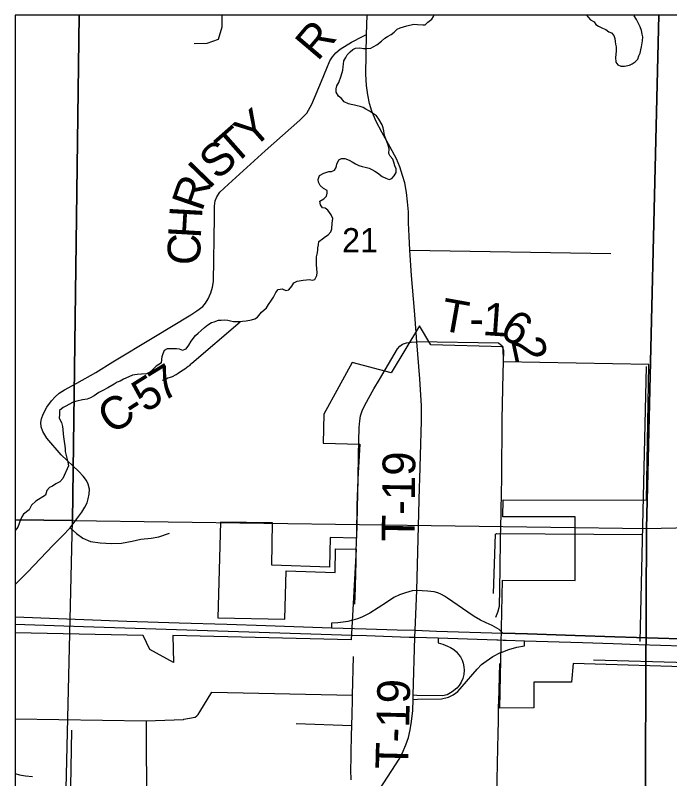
# Model space of a CAD drawing. Extents: x -8.5 to 18.7, y -20.3 to 7.
# Drawn here: x -8.459 to -6.189, y 4.29 to 6.938 of the extents above; entities that cross this region are included whole.
import ezdxf

# ---------------------------------------------------------------- set-up
doc = ezdxf.new("R2010")
doc.units = 0
for name, color, linetype in [('Default', 7, 'Continuous'), ('GM_X_City_Street', 7, 'Continuous'), ('GM_X_Corporation', 7, 'Continuous'), ('GM_X_County_Road', 7, 'Continuous'), ('GM_X_County_Road_Text', 7, 'Continuous'), ('GM_X_Interchange_Ramps', 7, 'Continuous'), ('GM_X_Minor_River', 7, 'Continuous'), ('GM_X_Rail_Line', 7, 'Continuous'), ('GM_X_Section', 7, 'Continuous'), ('GM_X_Section_Text', 7, 'Continuous'), ('GM_X_State_Route', 7, 'Continuous'), ('GM_X_Township_Road', 7, 'Continuous'), ('GM_X_Township_Road_Text', 7, 'Continuous'), ('GM_X_US_Route', 7, 'Continuous'), ('SH_Cut_Line', 7, 'Continuous')]:
    doc.layers.add(name, color=color, linetype=linetype)

msp = doc.modelspace()

# ---------------------------------------------------------------- linework, layer by layer
at = {"layer": 'Default'}
for points in [[(-8.2372, 6.938), (-8.4587, 6.938), (-8.4587, 5.1881), (-8.2602, 5.1852)], [(-6.2268, 6.938), (-8.2372, 6.938), (-8.2602, 5.1852), (-6.2691, 5.158)], [(-5.6649, 6.938), (-6.2268, 6.938), (-6.2691, 5.158), (-5.6605, 5.1719)], [(-8.4587, 5.1881), (-8.4587, 3.1783), (-8.308, 3.1769), (-8.2602, 5.1852)]]:
    msp.add_lwpolyline(points, close=True, dxfattribs=at)
at = {"layer": 'GM_X_City_Street'}
msp.add_line((-7.7774, 4.59), (-7.2888, 4.5798), dxfattribs=at)
for points in [[(-6.0668, 4.6758), (-6.5241, 4.6888), (-6.5294, 4.625), (-6.6599, 4.624), (-6.6607, 4.535), (-6.7778, 4.5349), (-6.7689, 4.9782), (-6.5174, 4.9773), (-6.5167, 5.1981), (-6.7673, 5.1977), (-6.7669, 5.2575), (-6.2701, 5.2558), (-6.262, 5.7269), (-6.7651, 5.7356), (-6.7671, 5.7877), (-7.0173, 5.7946), (-7.0564, 5.8602), (-7.1553, 5.6974), (-7.2898, 5.7334), (-7.3365, 5.6493), (-7.3888, 5.5548), (-7.3906, 5.4537), (-7.2638, 5.4504), (-7.2703, 5.3301), (-7.2751, 5.1245), (-7.3669, 5.1265), (-7.3686, 5.0231), (-7.5689, 5.0299), (-7.5665, 5.1774), (-7.7465, 5.1798), (-7.7558, 4.8481), (-7.5235, 4.8428), (-7.5194, 5.0107), (-7.3489, 5.0049), (-7.3476, 5.0876), (-7.2761, 5.0856), (-7.2937, 4.7709), (-7.9124, 4.786), (-7.9105, 4.6929), (-7.9916, 4.7383), (-8.0153, 4.7862), (-8.4587, 4.7954), (-8.4587, 2.5592)], [(-8.005, 4.4904), (-7.8758, 4.4954), (-7.874, 4.4958), (-7.8344, 4.5033), (-7.8291, 4.5074), (-7.8244, 4.5126), (-7.8187, 4.5211), (-7.7774, 4.59)]]:
    msp.add_lwpolyline(points, dxfattribs=at)
at = {"layer": 'GM_X_Corporation'}
msp.add_lwpolyline([(-0.1911, 6.938), (-8.4587, 6.938), (-8.4587, 1.1732)], dxfattribs=at)
at = {"layer": 'GM_X_County_Road'}
for points in [[(-8.4587, 4.9632), (-8.4161, 5.0061), (-8.3274, 5.0994), (-8.2948, 5.1327), (-8.2688, 5.16), (-8.2448, 5.1908), (-8.228, 5.2142), (-8.2171, 5.2314), (-8.2095, 5.2467), (-8.2054, 5.2608), (-8.2025, 5.2769), (-8.2018, 5.2946), (-8.2059, 5.3109), (-8.2115, 5.3245), (-8.2229, 5.3393), (-8.2382, 5.3554), (-8.2992, 5.413), (-8.3493, 5.4708), (-8.3634, 5.4942), (-8.3687, 5.51), (-8.3697, 5.5248), (-8.3678, 5.5384), (-8.3624, 5.5542), (-8.349, 5.5783), (-8.3332, 5.6004), (-8.3209, 5.614), (-8.3065, 5.6266), (-8.2878, 5.6383), (-8.2457, 5.6619), (-8.1796, 5.6993), (-8.1201, 5.7358), (-7.9781, 5.8213), (-7.8503, 5.8986), (-7.8291, 5.9122), (-7.8087, 5.928), (-7.7985, 5.9397), (-7.79, 5.9545), (-7.7808, 5.9747), (-7.7747, 5.9946), (-7.771, 6.0143), (-7.7678, 6.2389), (-7.7673, 6.2755), (-7.7656, 6.2937), (-7.7602, 6.308), (-7.7491, 6.3241), (-7.7192, 6.3518), (-7.592, 6.4675), (-7.4715, 6.5744), (-7.4474, 6.5978), (-7.4304, 6.6291), (-7.3966, 6.7091), (-7.3781, 6.7545), (-7.3672, 6.7803), (-7.3589, 6.7937), (-7.3473, 6.8078), (-7.3315, 6.8209), (-7.2928, 6.845), (-7.2547, 6.8644), (-7.2401, 6.8715)], [(-7.2173, 4.2203), (-7.1801, 4.2756), (-7.1278, 4.3572), (-7.1165, 4.377), (-7.1045, 4.4075), (-7.0952, 4.433), (-7.089, 4.4597), (-7.0841, 4.4877), (-7.0805, 4.5268), (-7.0793, 4.5648)], [(-8.4587, 4.4971), (-8.005, 4.4904), (-8.0049, 4.4864), (-8.0049, 4.4779)], [(-8.0049, 4.4779), (-8.0048, 4.4525), (-8.0037, 4.213), (-8.0015, 4.203), (-7.996, 4.1926), (-7.9883, 4.1843), (-7.9797, 4.1787), (-7.9712, 4.177), (-7.2987, 4.1876), (-7.2906, 4.1877), (-7.2385, 4.1886)]]:
    msp.add_lwpolyline(points, dxfattribs=at)
at = {"layer": 'GM_X_Interchange_Ramps'}
for points in [[(-7.0665, 4.9422), (-7.0817, 4.9411), (-7.1056, 4.935), (-7.1263, 4.9279), (-7.1454, 4.9181), (-7.1715, 4.9009), (-7.2286, 4.8643), (-7.2564, 4.8506), (-7.2722, 4.8444), (-7.2875, 4.8396)], [(-7.2875, 4.8396), (-7.3048, 4.8352), (-7.3216, 4.8322), (-7.3406, 4.83), (-7.362, 4.829), (-7.3621, 4.8135)], [(-6.9925, 4.7781), (-6.9917, 4.7608), (-6.9759, 4.756), (-6.9596, 4.7497), (-6.949, 4.7444), (-6.9383, 4.7375), (-6.9287, 4.7294), (-6.921, 4.7209), (-6.9144, 4.7124), (-6.9086, 4.7006), (-6.9051, 4.6902), (-6.9025, 4.6772), (-6.9019, 4.6667), (-6.9032, 4.6516), (-6.9068, 4.6376), (-6.9124, 4.6248), (-6.9193, 4.6127), (-6.9278, 4.6033), (-6.9431, 4.5906), (-6.9607, 4.5809), (-6.9773, 4.5774), (-7.0664, 4.5788), (-7.079, 4.5791)], [(-6.7739, 4.7278), (-6.7475, 4.7384), (-6.719, 4.7459), (-6.6926, 4.7507), (-6.6921, 4.7685)], [(-7.0793, 4.5648), (-7.0642, 4.566), (-6.98, 4.5665), (-6.9563, 4.5722), (-6.94, 4.5805), (-6.9242, 4.5924), (-6.9089, 4.609), (-6.8567, 4.67), (-6.8413, 4.6853), (-6.8256, 4.6972), (-6.8023, 4.7134), (-6.776, 4.727), (-6.7739, 4.7278)]]:
    msp.add_lwpolyline(points, dxfattribs=at)
at = {"layer": 'GM_X_Minor_River'}
for p, q in [((-7.8462, 5.7317), (-7.6793, 5.8743)), ((-6.2919, 4.7662), (-6.269, 5.7197)), ((-6.8007, 4.9327), (-6.7934, 5.1384)), ((-6.7934, 5.1384), (-6.7896, 5.1398)), ((-6.7896, 5.1398), (-6.2839, 5.1372)), ((-6.4529, 4.7018), (-6.0649, 4.6916))]:
    msp.add_line(p, q, dxfattribs=at)
for points in [[(-7.1858, 6.3788), (-7.1738, 6.3726), (-7.1624, 6.3688), (-7.1525, 6.3717), (-7.1441, 6.3808), (-7.1372, 6.3922), (-7.1379, 6.4051), (-7.1424, 6.4158), (-7.1461, 6.4279), (-7.1498, 6.4386), (-7.1588, 6.4493), (-7.1626, 6.4584), (-7.1625, 6.4744), (-7.1654, 6.4873), (-7.1691, 6.4965), (-7.1729, 6.5064), (-7.1773, 6.5186), (-7.1795, 6.5277), (-7.181, 6.5368), (-7.1832, 6.5475), (-7.1862, 6.5581), (-7.1982, 6.578), (-7.2057, 6.5887), (-7.2193, 6.5986), (-7.2298, 6.6048), (-7.2427, 6.6124), (-7.2518, 6.6186), (-7.2631, 6.6217), (-7.273, 6.624), (-7.2828, 6.6256), (-7.2934, 6.6287), (-7.3025, 6.6303), (-7.3176, 6.6372), (-7.3274, 6.6487), (-7.3372, 6.6579), (-7.3462, 6.6709), (-7.3461, 6.6823), (-7.343, 6.6929), (-7.3369, 6.7042), (-7.3284, 6.7277), (-7.3229, 6.7475), (-7.3214, 6.7588), (-7.3205, 6.7687), (-7.3189, 6.7801), (-7.3128, 6.7915), (-7.3074, 6.8013), (-7.2975, 6.8111), (-7.2883, 6.8187), (-7.2784, 6.8239), (-7.264, 6.8246), (-7.2512, 6.823), (-7.2398, 6.8229), (-7.2261, 6.8236), (-7.217, 6.8281), (-7.2048, 6.8356), (-7.1888, 6.8484), (-7.1773, 6.8582), (-7.1674, 6.8643), (-7.1545, 6.8718), (-7.1446, 6.8793), (-7.1347, 6.8899), (-7.124, 6.8944), (-7.1012, 6.9011), (-7.0769, 6.907), (-7.064, 6.9061), (-7.0458, 6.9045), (-7.0367, 6.9052), (-7.0276, 6.9135), (-7.0138, 6.9248), (-7.0077, 6.9339), (-7.0056, 6.938)], [(-6.4781, 6.938), (-6.4715, 6.9313), (-6.464, 6.9221), (-6.4511, 6.9152), (-6.4451, 6.906), (-6.436, 6.8999), (-6.4217, 6.893), (-6.4103, 6.8883), (-6.4005, 6.8807), (-6.3915, 6.8768), (-6.3824, 6.8676), (-6.3794, 6.8577), (-6.378, 6.8471), (-6.3765, 6.8372), (-6.3751, 6.8281), (-6.3752, 6.8144), (-6.376, 6.8015), (-6.3769, 6.7916), (-6.3754, 6.7756), (-6.3694, 6.7657), (-6.3581, 6.7611), (-6.346, 6.7618), (-6.3285, 6.7647), (-6.3194, 6.7692), (-6.3087, 6.7767), (-6.2995, 6.7858), (-6.2957, 6.7972), (-6.2918, 6.807), (-6.2887, 6.8184), (-6.2871, 6.829), (-6.2839, 6.8488), (-6.2823, 6.8632), (-6.2845, 6.8723), (-6.2867, 6.8853), (-6.2912, 6.8974), (-6.2987, 6.9119), (-6.3047, 6.9234), (-6.3122, 6.9356), (-6.3137, 6.938)], [(-7.9517, 5.7325), (-7.9492, 5.7537), (-7.9461, 5.7643), (-7.9407, 5.7757), (-7.9308, 5.7817), (-7.921, 5.7816), (-7.9104, 5.7823), (-7.8997, 5.7823), (-7.8899, 5.7807), (-7.8785, 5.776), (-7.8656, 5.7805), (-7.8564, 5.7934), (-7.8488, 5.807), (-7.8335, 5.8274), (-7.8243, 5.835), (-7.8144, 5.844), (-7.8029, 5.8546), (-7.7907, 5.8636), (-7.7778, 5.8727), (-7.7687, 5.8741), (-7.7542, 5.8801), (-7.7451, 5.8808), (-7.7345, 5.8815), (-7.7216, 5.8799), (-7.7118, 5.8783), (-7.7019, 5.876), (-7.6807, 5.8759), (-7.6708, 5.8773), (-7.6579, 5.878), (-7.6397, 5.8817), (-7.6283, 5.8846), (-7.6191, 5.8907), (-7.6046, 5.908), (-7.5878, 5.9231), (-7.5802, 5.9352), (-7.5725, 5.9466), (-7.5626, 5.9602), (-7.5556, 5.9761), (-7.5464, 5.9867), (-7.5328, 5.9889), (-7.5207, 5.9835), (-7.5101, 5.9857), (-7.5001, 5.9986), (-7.4932, 6.0099), (-7.481, 6.0159), (-7.4605, 6.0196), (-7.4491, 6.0203), (-7.4385, 6.021), (-7.4294, 6.0186), (-7.4203, 6.0216), (-7.4126, 6.0352), (-7.4118, 6.0451), (-7.4139, 6.0717), (-7.4137, 6.0998), (-7.4121, 6.109), (-7.4098, 6.1219), (-7.409, 6.131), (-7.4074, 6.1416), (-7.4058, 6.1537), (-7.3936, 6.162), (-7.3829, 6.1703), (-7.3738, 6.1763), (-7.3639, 6.1862), (-7.3607, 6.1968), (-7.3599, 6.2173), (-7.3575, 6.2332), (-7.3627, 6.2454), (-7.3747, 6.2615), (-7.3838, 6.2684), (-7.3929, 6.2699), (-7.4004, 6.2806), (-7.4026, 6.2928), (-7.3881, 6.3011), (-7.3797, 6.3101), (-7.3766, 6.3207), (-7.3765, 6.3299), (-7.3894, 6.3375), (-7.4015, 6.3475), (-7.4067, 6.3589), (-7.4081, 6.3681), (-7.4035, 6.3817), (-7.389, 6.39), (-7.3716, 6.3959), (-7.3617, 6.3959), (-7.3518, 6.4004), (-7.3457, 6.4094), (-7.3433, 6.4216), (-7.3364, 6.436), (-7.3273, 6.4412), (-7.3159, 6.4412), (-7.3008, 6.4358), (-7.2902, 6.4296), (-7.2788, 6.4227), (-7.2675, 6.4173), (-7.2554, 6.4134), (-7.2455, 6.4111), (-7.2312, 6.408), (-7.2221, 6.4026), (-7.2115, 6.3972), (-7.2024, 6.3918), (-7.1858, 6.3788)], [(-7.9517, 5.7325), (-7.9702, 5.721), (-7.9817, 5.709), (-7.9916, 5.7), (-8.0031, 5.694), (-8.0206, 5.6927), (-8.0358, 5.6921), (-8.0517, 5.6892), (-8.0647, 5.6832), (-8.083, 5.6751), (-8.0945, 5.6691), (-8.1051, 5.6647), (-8.1158, 5.6587), (-8.1372, 5.646), (-8.1548, 5.6363), (-8.1693, 5.6296), (-8.1853, 5.6184), (-8.1983, 5.6109), (-8.209, 5.6064), (-8.225, 5.6043), (-8.2455, 5.5992), (-8.2577, 5.5955), (-8.273, 5.5873), (-8.2837, 5.5821), (-8.2928, 5.5769), (-8.3058, 5.5664), (-8.3052, 5.5527), (-8.3069, 5.5398), (-8.2987, 5.5253), (-8.295, 5.5116), (-8.2943, 5.501), (-8.2922, 5.4858), (-8.2916, 5.4759), (-8.2887, 5.4592), (-8.2873, 5.444), (-8.2859, 5.4341), (-8.2852, 5.4242), (-8.2838, 5.4151), (-8.2765, 5.3877), (-8.2743, 5.3755), (-8.2938, 5.3309), (-8.3037, 5.3196), (-8.3182, 5.3121), (-8.3297, 5.3047), (-8.3404, 5.2994), (-8.3496, 5.2897), (-8.3536, 5.273), (-8.3872, 5.2528), (-8.4025, 5.2385), (-8.411, 5.2227), (-8.4302, 5.2069), (-8.4363, 5.1979), (-8.4418, 5.1858), (-8.4457, 5.1744), (-8.4503, 5.1623), (-8.4587, 5.1504)], [(-7.9476, 5.6719), (-7.9423, 5.6741), (-7.9354, 5.677), (-7.9301, 5.68), (-7.9209, 5.6829), (-7.9133, 5.6851), (-7.9011, 5.6917), (-7.8934, 5.6969), (-7.8819, 5.7043), (-7.8712, 5.7118), (-7.8596, 5.7207), (-7.8535, 5.7236), (-7.8481, 5.7289), (-7.8452, 5.7327)]]:
    msp.add_lwpolyline(points, dxfattribs=at)
at = {"layer": 'GM_X_Rail_Line'}
for points in [[(-8.2172, 4.0449), (-8.2409, 4.0819), (-8.2545, 4.1155), (-8.2656, 4.1515), (-8.2672, 4.1959), (-8.2624, 4.4579)], [(-8.4587, 4.3079), (-8.4435, 4.3026), (-8.4228, 4.2999), (-8.3986, 4.2978)]]:
    msp.add_lwpolyline(points, dxfattribs=at)
at = {"layer": 'GM_X_Section'}
for points in [[(-8.2602, 5.1852), (-6.2691, 5.158), (-6.2755, 3.8141), (-6.7916, 3.8218), (-6.8057, 3.1632), (-8.308, 3.1769)], [(-6.2691, 5.158), (-5.6605, 5.1719), (-4.2745, 5.1557), (-4.3131, 3.8082), (-6.2755, 3.8141)]]:
    msp.add_lwpolyline(points, close=True, dxfattribs=at)
at = {"layer": 'GM_X_State_Route'}
for p, q in [((-7.0657, 5.8048), (-7.0722, 5.8842)), ((-7.0665, 4.9422), (-7.0568, 5.2999)), ((-6.7673, 4.795), (-6.7805, 4.8069))]:
    msp.add_line(p, q, dxfattribs=at)
for points in [[(-7.0722, 5.8842), (-7.0747, 5.9139), (-7.0844, 6.0355), (-7.0898, 6.1234), (-7.093, 6.1722), (-7.0945, 6.2184), (-7.0955, 6.2558), (-7.0979, 6.2903), (-7.1018, 6.3229), (-7.1076, 6.3564), (-7.1154, 6.3827), (-7.1251, 6.4123), (-7.1368, 6.44), (-7.1587, 6.4799), (-7.1878, 6.5329), (-7.2073, 6.5698), (-7.2219, 6.6048), (-7.2301, 6.6316), (-7.236, 6.6617), (-7.2408, 6.6938), (-7.2428, 6.7336), (-7.2401, 6.8715), (-7.2384, 6.938)], [(-7.0568, 5.2999), (-7.056, 5.3294), (-7.0531, 5.4103), (-7.0494, 5.5311), (-7.0501, 5.5826), (-7.0555, 5.6769), (-7.0657, 5.8048)], [(-7.0793, 4.5648), (-7.079, 4.5791), (-7.0727, 4.7803), (-7.0718, 4.8044), (-7.0665, 4.9422)], [(-6.7805, 4.8069), (-6.8048, 4.8217), (-6.8256, 4.8301), (-6.8448, 4.8392), (-6.8669, 4.8518), (-6.8894, 4.8673), (-6.9595, 4.9164), (-6.9698, 4.9231), (-6.981, 4.929), (-6.9929, 4.934), (-7.0056, 4.9374), (-7.0289, 4.9404), (-7.0665, 4.9422)], [(-8.4587, 4.8262), (-8.2217, 4.8174), (-7.3625, 4.7897), (-7.2925, 4.7875)], [(-5.711, 4.7602), (-5.9427, 4.7681), (-6.1541, 4.7749), (-6.3792, 4.782), (-6.5168, 4.7866), (-6.6826, 4.7919), (-6.7673, 4.795)], [(-7.2925, 4.7875), (-7.2405, 4.7859), (-7.0927, 4.781)], [(-7.0927, 4.781), (-7.0727, 4.7803), (-6.9925, 4.7781)], [(-6.9925, 4.7781), (-6.7882, 4.7716), (-6.7843, 4.7714)], [(-6.7843, 4.7714), (-6.7668, 4.7708), (-6.7566, 4.7705), (-6.6921, 4.7685)], [(-6.6921, 4.7685), (-6.492, 4.7618), (-6.3857, 4.7585), (-6.2967, 4.7555), (-6.1455, 4.7506), (-5.9801, 4.7453), (-5.8594, 4.7411), (-5.7336, 4.7369)]]:
    msp.add_lwpolyline(points, dxfattribs=at)
at = {"layer": 'GM_X_Township_Road'}
for p, q in [((-7.0898, 6.1234), (-6.3927, 6.1118)), ((-6.7756, 5.1234), (-6.7749, 5.163)), ((-7.276, 5.075), (-7.2752, 5.1148)), ((-6.7759, 5.1035), (-6.7756, 5.1234)), ((-7.2768, 5.0353), (-7.276, 5.075)), ((-6.7775, 5.0052), (-6.7772, 5.0245)), ((-7.2888, 4.5798), (-7.2854, 4.7135)), ((-6.7807, 4.5989), (-6.7784, 4.6892)), ((-7.2915, 4.474), (-7.2905, 4.5127)), ((-7.4842, 4.4807), (-7.2915, 4.474))]:
    msp.add_line(p, q, dxfattribs=at)
for points in [[(-7.8387, 6.8401), (-7.793, 6.8411), (-7.7542, 6.8547), (-7.7415, 6.8984), (-7.7408, 6.938)], [(-7.1955, 5.6746), (-7.1329, 5.7806), (-7.1251, 5.7901), (-7.1158, 5.7975), (-7.1015, 5.8019), (-7.0856, 5.8042), (-7.0657, 5.8048)], [(-6.7662, 5.695), (-6.7661, 5.697), (-6.7649, 5.7735), (-6.7705, 5.7903), (-6.7831, 5.8001), (-7.0657, 5.8048)], [(-6.7739, 5.2224), (-6.7717, 5.3339), (-6.77, 5.5366), (-6.7662, 5.695)], [(-7.2681, 5.4127), (-7.2661, 5.5084), (-7.2639, 5.5315), (-7.2612, 5.5486), (-7.256, 5.5655), (-7.2466, 5.5852), (-7.2147, 5.6421), (-7.1955, 5.6746)], [(-7.2752, 5.1148), (-7.2747, 5.1406), (-7.2727, 5.2377), (-7.2699, 5.329), (-7.2681, 5.4127)], [(-6.7749, 5.163), (-6.7741, 5.2106), (-6.7739, 5.2224)], [(-8.2688, 5.16), (-8.2465, 5.1398), (-8.2239, 5.1237), (-8.1983, 5.113), (-8.1643, 5.1077), (-8.1247, 5.1053), (-8.0899, 5.107), (-8.0532, 5.1135), (-8.0229, 5.1203), (-7.9874, 5.1245), (-7.9606, 5.1288), (-7.9234, 5.1415)], [(-6.7772, 5.0245), (-6.7771, 5.0361), (-6.7759, 5.1035)], [(-7.2806, 4.8954), (-7.2791, 4.9507), (-7.2774, 5.0074), (-7.2768, 5.0353)], [(-6.7784, 4.9469), (-6.778, 4.9647), (-6.7775, 5.0052)], [(-6.7921, 4.8499), (-6.7848, 4.8672), (-6.7795, 4.8879), (-6.7784, 4.9469)], [(-6.7824, 4.5338), (-6.7809, 4.5924), (-6.7807, 4.5989)], [(-7.2905, 4.5127), (-7.2903, 4.5195), (-7.2894, 4.5569)], [(-7.2894, 4.5569), (-7.2893, 4.5591), (-7.2892, 4.5631), (-7.2888, 4.5798)], [(-6.7845, 4.4297), (-6.783, 4.5067), (-6.7826, 4.5233), (-6.7824, 4.5338)], [(-7.2933, 4.3995), (-7.2928, 4.4204), (-7.2924, 4.4384), (-7.2915, 4.474)], [(-6.7865, 4.3256), (-6.7849, 4.4128), (-6.7845, 4.4297)], [(-7.2941, 4.2863), (-7.2953, 4.3207), (-7.2943, 4.3624), (-7.2933, 4.3995)], [(-6.787, 4.2997), (-6.787, 4.3022), (-6.7865, 4.3256)], [(-6.7901, 4.1964), (-6.7875, 4.2746), (-6.787, 4.2997)]]:
    msp.add_lwpolyline(points, dxfattribs=at)
at = {"layer": 'GM_X_US_Route'}
for points in [[(-8.4587, 4.8517), (-8.0723, 4.8366), (-7.8906, 4.8307), (-7.7254, 4.8255), (-7.5895, 4.8209), (-7.3621, 4.8135)], [(-8.4587, 4.8262), (-8.2217, 4.8174), (-7.3625, 4.7897), (-7.2925, 4.7875)], [(-7.3621, 4.8135), (-7.2416, 4.8098), (-7.134, 4.8064), (-7.0718, 4.8044), (-6.9981, 4.8016), (-6.7673, 4.795)], [(-6.7673, 4.795), (-6.6826, 4.7919), (-6.5168, 4.7866), (-6.3792, 4.782), (-6.1541, 4.7749), (-5.9427, 4.7681), (-5.711, 4.7602)], [(-7.2925, 4.7875), (-7.2405, 4.7859), (-7.0927, 4.781)], [(-7.0927, 4.781), (-7.0727, 4.7803), (-6.9925, 4.7781)], [(-6.9925, 4.7781), (-6.7882, 4.7716), (-6.7843, 4.7714)], [(-6.7843, 4.7714), (-6.7668, 4.7708), (-6.7566, 4.7705), (-6.6921, 4.7685)], [(-6.6921, 4.7685), (-6.492, 4.7618), (-6.3857, 4.7585), (-6.2967, 4.7555), (-6.1455, 4.7506), (-5.9801, 4.7453), (-5.8594, 4.7411), (-5.7336, 4.7369)]]:
    msp.add_lwpolyline(points, dxfattribs=at)
at = {"layer": 'SH_Cut_Line'}
msp.add_lwpolyline([(18.7413, 6.938), (-8.4587, 6.938), (-8.4587, -10.6981)], dxfattribs=at)

# ---------------------------------------------------------------- texts
at = {"layer": 'GM_X_County_Road_Text'}
for s, rotation, p in [('R', 49.6942, (-7.41, 6.7756)), ('Y', 41.4055, (-7.6361, 6.4705)), ('T', 41.3944, (-7.6999, 6.4143)), ('S', 41.9243, (-7.7567, 6.3633)), ('I', 45.9549, (-7.7876, 6.3312)), ('R', 70.9689, (-7.8112, 6.254)), ('H', 86.6795, (-7.8154, 6.1623)), ('C', 88.2903, (-7.8182, 6.0698)), ('7', 31.526, (-7.9485, 5.5941)), ('5', 32.0214, (-8.0076, 5.5571)), ('C', 33.5223, (-8.124, 5.4809)), ('-', 32.6508, (-8.0466, 5.5321))]:
    msp.add_text(s, height=0.1136, rotation=rotation, dxfattribs=at).set_placement(p)
at = {"layer": 'GM_X_Section_Text'}
msp.add_text('21', height=0.08371, rotation=0, dxfattribs=at).set_placement((-7.3252, 6.1159))
at = {"layer": 'GM_X_Township_Road_Text'}
for s, height, rotation, p in [('T', 0.1136, 349.8777, (-6.989, 5.8461)), ('1', 0.1136, 356.0646, (-6.8401, 5.8291)), ('6', 0.1136, 327.5773, (-6.7849, 5.8289)), ('-', 0.1136, 359.5951, (-6.8845, 5.8293)), ('2', 0.1136, 282.0486, (-6.7396, 5.8108)), ('T-19', 0.11364, 89.2981, (-7.0746, 5.1118)), ('T-19', 0.11364, 88.6086, (-7.0963, 4.3216))]:
    msp.add_text(s, height=height, rotation=rotation, dxfattribs=at).set_placement(p)

doc.saveas('drawing.dxf')
